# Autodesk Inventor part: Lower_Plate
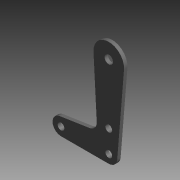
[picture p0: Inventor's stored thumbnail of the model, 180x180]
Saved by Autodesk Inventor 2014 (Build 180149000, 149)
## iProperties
Shininess: 15.0
Length Units: 11272
Angle Units: 11279
Time Units: 11290
Mass Units: 11283
Length Display Precision: 2
Angle Display Precision: 1
Compacted: True
Created: 1999-05
Part Number: Lower_Plate
Document SubType Name: Modeling
Designer: Administrator
Density: 8.83 g/cm^3
Material: NICU, Monel 400
Appearance: Metal - Silver
Density: 8.83
Volumn: 8.899101648082546
Area: 68.18129680210748
PropertySet Name: Model Information
Control State: 0
Master: False
Checked Out: False
Author: Administrator
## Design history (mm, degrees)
node "y-z Plane"
  node "x-z Plane"
  node "x-y Plane"
node "Extrusion1" dims "d6" = 3.175, "d7" = 0
  sketch "Sketch1"
    geometry: L1 (-44.45, -84.074)-(0, -84.074); L2 (7.847, -76.856)-(14.175, -1.185); L3 (-14.203, -0.776)-(-11.188, -55.993); L4 (-17.87, -64.207)-(-45.63, -68.415); L5 (0, 0)-(0, -76.2); A1 r 7.874 centre (0, -76.2) between (0, -84.074) and (7.847, -76.856); A2 r 14.224 centre (0, 0) between (14.175, -1.185) and (-14.203, -0.776); A3 r 7.874 centre (-19.05, -56.422) between (-17.87, -64.207) and (-11.188, -55.993); A4 r 7.874 centre (-44.45, -76.2) between (-45.63, -68.415) and (-44.45, -84.074); 1 further point
    constraints: 10 end point, 8 point on circle, 8 tangent, 4 centre point, 1 coincident, 1 horizontal, 1 horizontal alignment, 1 perpendicular, 1 vertical alignment
    dimensions: "d0" = 76.2 distance of L5.end L5.start; "d1" = 44.45 distance of A4.centre L5.end; "d2" = 14.224 radius of A2; "d3" = 7.874 radius of A3; "d4" = 7.874 radius of A4; "d5" = 19.05 horizontal distance of A3.centre L5.end; "d23" = 56.42223 vertical distance of A3.centre L5.start
node "Hole1" dims "d9" = 6.35, "d10" = 9.525, "d11" = 6.35, "d12" = 60 deg, "d13" = 19.05, "d14" = 118 deg
  sketch "Sketch2"
    geometry: A1 r 7.874 centre (0, -76.2) between (0, -84.074) and (7.847, -76.856) reference; A2 r 7.874 centre (-44.45, -76.2) between (-45.63, -68.415) and (-44.45, -84.074) reference; 1 further point
    dimensions: "d8" = 20.574 distance of point (0, -55.626) A1.centre
node "Hole2" dims "d15" = 7.874, "d16" = 9.525, "d17" = 6.35, "d18" = 60 deg, "d19" = 19.05, "d20" = 118 deg
  sketch "Sketch3"
    geometry: A1 r 14.224 centre (0, 0) between (14.175, -1.185) and (-14.203, -0.776) reference
body "Solid1"
